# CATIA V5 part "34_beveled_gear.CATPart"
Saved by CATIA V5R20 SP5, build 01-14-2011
Part number: 34_beveled_gear
Bounding box of the stored display mesh (mm): x -22.323 to 22.323, y 11.039 to 55.685, z -70.294 to -39.012
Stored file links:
  C:\Documents and Settings\anizard\Bureau\13\34_beveled_gear.CATPart
  C:\Documents and Settings\anizard\Bureau\13\anizard.CATProduct
  C:\Documents and Settings\anizard\Bureau\13\21_casing.CATPart
  D:\Documents\T\2011-2012\CFAO\ThinkMotion\7\SqueletteV.CATPart
  D:\Documents\T\2011-2012\CFAO\ThinkMotion\2\32_Anular_gear.CATPart
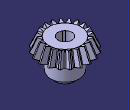
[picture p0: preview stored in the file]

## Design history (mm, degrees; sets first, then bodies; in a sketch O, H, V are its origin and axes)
External parameters (linked from other documents)
  External.Z2.1 = 20
  External.module.1 = 2 mm
Set1
  Line1: linked copy from another document
  Point1: linked copy from another document
  Line2: linked copy from another document
  Point2: linked copy from another document
  Line3: linked copy from another document
  Sketch1, origin (0, -15.7121, -39.5984), H (-1, 0, 0), V (0, -0.931, 0.3651), geometry linked from another document
  Sketch2, origin (0, -10.3492, -26.6635), H (-1, 0, 0), V (0, -0.931, 0.3651), geometry linked from another document
  Point3: linked copy from another document
  Line4: linked copy from another document
  Line5: linked copy from another document
  Point4: linked copy from another document
  Plane1: linked copy from another document
  Point5: linked copy from another document
  Point6: linked copy from another document
Body1 (main body)
  Sketch3 on yz-plane, origin (0, 0, 0), H (0, 1, 0), V (0, 0, 1)
    line L1 (27.3619, -40.2938) -> (19.2345, -40.2938)
    line L2 (19.2345, -40.2938) -> (15.2247, -51.7305)
    line L3 (15.2247, -51.7305) -> (20.8619, -53.9412)
    line L4 (20.8619, -53.9412) -> (20.8619, -66.2938)
    line L5 (27.3619, -70.2938) -> (27.3619, -40.2938)
    line L6 (20.8619, -66.2938) -> (24.8619, -66.2938)
    line L7 (24.8619, -66.2938) -> (24.8619, -70.2938)
    line L8 (24.8619, -70.2938) -> (27.3619, -70.2938)
    reference projected point E1 (13.3619, -51) from Point1
    reference projected point E2 (17.5605, -40.2938) from Point2
    reference projected line E3 (8.4086, -71.1714) -> (33.151, -0.6018) from Line3
    reference projected line E4 (5.8217, -70.2275) -> (33.1235, -0.6081) from Line4
    reference projected point E5 (27.3619, -40.2938) from Point4
    reference intersected line E6 through (0, -70.2938) direction (1, 0) from Plane1
    reference projected line E7 (33.3619, 0) -> (33.3619, -190) from Line2
    reference projected line E8 (33.3619, 0) -> (33.3619, -190) from Line2
    distance L8 L6 = 4
    distance E7 L7 = 8.5
    distance E8 L4 = 12.5
    horizontal: L1 H, L6 H, L8 H
    vertical: L4 V, L5 V, L7 V
    coincidence: L2 E3, L3 E1, L1 E2, L5 E5, L8 E6
    perpendicularity: L3 E4
  Shaft1: profile Sketch3, axis Line5, angle 360
  Loft1: solid, Sections (Sketch1; Sketch2)
  CircPattern1: of the body so far, instances 21 {= External.Z2.1 +1}, angular step 18 {= 360deg/External.Z2.1}, axis from Line2
  Sketch4 on yz-plane, origin (0, 0, 0), H (0, 1, 0), V (0, 0, 1)
    line L1 (33.3619, -40.2938) -> (19.2345, -40.2938)
    point P2 (19.2345, -40.2938)
    line L2 (19.2345, -40.2938) -> (13.5605, -38.0687)
    line L3 (13.5605, -34.2088) -> (33.3619, -34.2088)
    line L4 (33.3619, -34.2088) -> (33.3619, -40.2938)
    reference projected point E1 (17.5605, -40.2938) from Point2
    reference projected point E2 (16.7739, -37.2088) from Point3
    reference projected line E3 (5.8217, -70.2275) -> (33.1235, -0.6081) from Line4
    line L5 (10.0794, -49.7127) -> (17.0879, -52.4612)
    line L6 (17.0879, -52.4612) -> (16.4257, -54.3498)
    line L7 (16.4257, -54.3498) -> (10.0794, -51.861)
    reference projected line E4 (5.8217, -70.2275) -> (33.1235, -0.6081) from Line4
    reference projected point E5 (13.3619, -51) from Point1
    reference projected line E6 (8.4086, -71.1714) -> (33.151, -0.6018) from Line3
    reference projected line E7 (8.4086, -71.1714) -> (33.151, -0.6018) from Line3
    line L8 (10.0794, -51.861) -> (10.0794, -49.7127)
    line L9 (13.5605, -34.2088) -> (13.5605, -38.0687)
    reference projected point E8 (11.0794, -49.9824) from Point5
    reference projected line E9 (33.3619, 0) -> (33.3619, -190) from Line2
    reference projected point E10 (17.5605, -40.2938) from Point6
    distance L3 E2 = 3
    distance E6 L6 = 2
    distance L7 L5 = 2
    distance E8 L8 = 1
    distance E10 L9 = 4
    horizontal: L1 H, L3 H
    vertical: L4 V, L9 V, L8 V
    coincidence: E1 L1, L5 E5, P2 E7, L4 E9
    perpendicularity: L2 E3, L5 E4
  Groove1: profile Sketch4, axis Line2, angle 360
